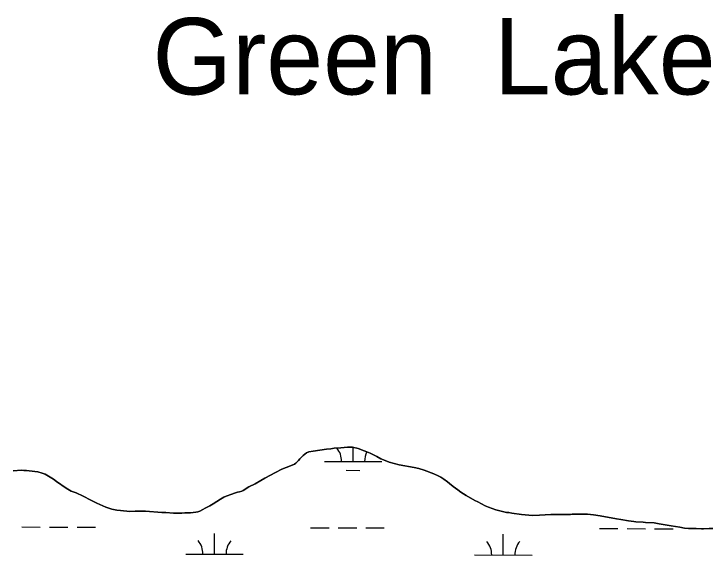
# Model space of a CAD drawing. Extents: x 3161615 to 3199515, y 867541 to 892976.
# Drawn here: x 3194005 to 3195219, y 874541 to 875483 of the extents above; entities that cross this region are included whole.
import ezdxf

# ---------------------------------------------------------------- set-up
doc = ezdxf.new("R2010")
doc.units = 0
for name, color, linetype in [('V-RIVR-IDEN', 7, 'Continuous'), ('V-SITE-VEGE', 7, 'Continuous'), ('V-TOPO-SHOR', 7, 'Continuous'), ('V-WETL-SWMP', 7, 'Continuous')]:
    doc.layers.add(name, color=color, linetype=linetype)

msp = doc.modelspace()

# ---------------------------------------------------------------- linework, layer by layer
at = {"layer": 'V-SITE-VEGE'}
for p, q in [((3194548.7, 874725.6), (3194525.2, 874722.4)), ((3194556.2, 874726.4), (3194548.7, 874725.6)), ((3194561.9, 874727.2), (3194556.2, 874726.4)), ((3194573.6, 874728.1), (3194561.9, 874727.2)), ((3194585, 874729.2), (3194573.6, 874728.1)), ((3194593.5, 874729), (3194585, 874729.2)), ((3194603.4, 874726.6), (3194593.5, 874729)), ((3194614, 874722.8), (3194603.4, 874726.6)), ((3194618.5, 874721), (3194614, 874722.8)), ((3194507.8, 874714.7), (3194502.2, 874709)), ((3194513.9, 874719), (3194507.8, 874714.7)), ((3194517.9, 874720.8), (3194513.9, 874719)), ((3194525.2, 874722.4), (3194517.9, 874720.8)), ((3194624.6, 874718.4), (3194618.5, 874721)), ((3194636.1, 874712.7), (3194624.6, 874718.4)), ((3194643.2, 874708.9), (3194636.1, 874712.7)), ((3194492.7, 874699.4), (3194485.8, 874696.5)), ((3194495.3, 874701), (3194492.7, 874699.4)), ((3194497.7, 874703.3), (3194495.3, 874701)), ((3194499.7, 874706.1), (3194497.7, 874703.3)), ((3194502.2, 874709), (3194499.7, 874706.1)), ((3194650.5, 874705.7), (3194643.2, 874708.9)), ((3194657.7, 874703.1), (3194650.5, 874705.7)), ((3194674.7, 874698.3), (3194657.7, 874703.1)), ((3194018.6, 874688.8), (3194004, 874688.2)), ((3194022.3, 874688.6), (3194018.6, 874688.8)), ((3194027.1, 874688.5), (3194022.3, 874688.6)), ((3194032, 874688.1), (3194027.1, 874688.5)), ((3194046.6, 874685.9), (3194032, 874688.1)), ((3194470.8, 874690.6), (3194459.7, 874685.3)), ((3194485.8, 874696.5), (3194470.8, 874690.6)), ((3194701.1, 874693.5), (3194674.7, 874698.3)), ((3194708.8, 874691.7), (3194701.1, 874693.5)), ((3194718.5, 874689.1), (3194708.8, 874691.7)), ((3194735.4, 874682.9), (3194718.5, 874689.1)), ((3194054.1, 874683.9), (3194046.6, 874685.9)), ((3194059.4, 874681.9), (3194054.1, 874683.9)), ((3194068.5, 874677.1), (3194059.4, 874681.9)), ((3194074.2, 874673.2), (3194068.5, 874677.1)), ((3194441.1, 874675.3), (3194434.2, 874671)), ((3194459.7, 874685.3), (3194441.1, 874675.3)), ((3194742.5, 874679.5), (3194735.4, 874682.9)), ((3194747.5, 874676.7), (3194742.5, 874679.5)), ((3194752.4, 874673.3), (3194747.5, 874676.7)), ((3194079.5, 874669.2), (3194074.2, 874673.2)), ((3194096, 874657.7), (3194079.5, 874669.2)), ((3194424.3, 874665.3), (3194413.6, 874660)), ((3194434.2, 874671), (3194424.3, 874665.3)), ((3194758.9, 874668.6), (3194752.4, 874673.3)), ((3194762.2, 874665.6), (3194758.9, 874668.6)), ((3194768.9, 874660.4), (3194762.2, 874665.6)), ((3194104.9, 874652.7), (3194096, 874657.7)), ((3194113.2, 874649.7), (3194104.9, 874652.7)), ((3194393.7, 874650.6), (3194388.5, 874649.1)), ((3194397.2, 874651.4), (3194393.7, 874650.6)), ((3194401.2, 874652.6), (3194397.2, 874651.4)), ((3194403.9, 874653.7), (3194401.2, 874652.6)), ((3194413.6, 874660), (3194403.9, 874653.7)), ((3194776.6, 874654.9), (3194768.9, 874660.4)), ((3194781.9, 874650.7), (3194776.6, 874654.9)), ((3194791.3, 874645), (3194781.9, 874650.7)), ((3194125.4, 874644.1), (3194113.2, 874649.7)), ((3194138.8, 874636.8), (3194125.4, 874644.1)), ((3194364.4, 874638.9), (3194351.5, 874630.7)), ((3194370.3, 874642.2), (3194364.4, 874638.9)), ((3194374.3, 874644), (3194370.3, 874642.2)), ((3194384.2, 874647.3), (3194374.3, 874644)), ((3194388.5, 874649.1), (3194384.2, 874647.3)), ((3194806.1, 874636.4), (3194791.3, 874645)), ((3194149.2, 874631.4), (3194138.8, 874636.8)), ((3194165, 874625), (3194149.2, 874631.4)), ((3194346, 874627.3), (3194337.9, 874623.2)), ((3194351.5, 874630.7), (3194346, 874627.3)), ((3194811.6, 874633.8), (3194806.1, 874636.4)), ((3194824.6, 874626.9), (3194811.6, 874633.8)), ((3194830, 874624.5), (3194824.6, 874626.9)), ((3194175.2, 874621.5), (3194165, 874625)), ((3194183.9, 874619.4), (3194175.2, 874621.5)), ((3194190.8, 874619), (3194183.9, 874619.4)), ((3194206.6, 874617.4), (3194190.8, 874619)), ((3194215.9, 874617.9), (3194206.6, 874617.4)), ((3194233.9, 874617.9), (3194215.9, 874617.9)), ((3194262.3, 874615.4), (3194233.9, 874617.9)), ((3194269.4, 874615.2), (3194262.3, 874615.4)), ((3194282.6, 874614.1), (3194269.4, 874615.2)), ((3194287.5, 874614.1), (3194282.6, 874614.1)), ((3194297, 874614.3), (3194287.5, 874614.1)), ((3194302.5, 874614.7), (3194297, 874614.3)), ((3194306.5, 874614.6), (3194302.5, 874614.7)), ((3194312.2, 874615), (3194306.5, 874614.6)), ((3194321.7, 874616), (3194312.2, 874615)), ((3194325, 874616.5), (3194321.7, 874616)), ((3194328.2, 874617.9), (3194325, 874616.5)), ((3194333.7, 874620.7), (3194328.2, 874617.9)), ((3194337.9, 874623.2), (3194333.7, 874620.7)), ((3194842.6, 874620.3), (3194830, 874624.5)), ((3194854.4, 874617.1), (3194842.6, 874620.3)), ((3194861.3, 874615.7), (3194854.4, 874617.1)), ((3194865.2, 874615.3), (3194861.3, 874615.7)), ((3194870.8, 874614.3), (3194865.2, 874615.3)), ((3194887.3, 874612.2), (3194870.8, 874614.3)), ((3194900.4, 874611), (3194887.3, 874612.2)), ((3194907.3, 874610.2), (3194900.4, 874611)), ((3194918.9, 874610.9), (3194907.3, 874610.2)), ((3194938.3, 874611.8), (3194918.9, 874610.9)), ((3194948.7, 874611.8), (3194938.3, 874611.8)), ((3194954.4, 874612), (3194948.7, 874611.8)), ((3194960.8, 874611.7), (3194954.4, 874612)), ((3194972.4, 874612.1), (3194960.8, 874611.7)), ((3194975.8, 874612.5), (3194972.4, 874612.1)), ((3194982.5, 874612.3), (3194975.8, 874612.5)), ((3194985.8, 874612.6), (3194982.5, 874612.3)), ((3195002, 874612.6), (3194985.8, 874612.6)), ((3195012.9, 874611.4), (3195002, 874612.6)), ((3195024.5, 874609.5), (3195012.9, 874611.4)), ((3195052.7, 874604.3), (3195024.5, 874609.5)), ((3195060, 874603.3), (3195052.7, 874604.3)), ((3195073.4, 874600.9), (3195060, 874603.3)), ((3195082.7, 874599.6), (3195073.4, 874600.9)), ((3195086.2, 874599.2), (3195082.7, 874599.6)), ((3195098.9, 874598.4), (3195086.2, 874599.2)), ((3195103, 874598), (3195098.9, 874598.4)), ((3195118.2, 874597.7), (3195103, 874598)), ((3195126.9, 874595.7), (3195118.2, 874597.7)), ((3195147.8, 874592.5), (3195126.9, 874595.7)), ((3195162.6, 874589.7), (3195147.8, 874592.5)), ((3195170.7, 874588.4), (3195162.6, 874589.7)), ((3195177.8, 874587.6), (3195170.7, 874588.4)), ((3195190.8, 874587.4), (3195177.8, 874587.6)), ((3195200.1, 874587), (3195190.8, 874587.4)), ((3195204, 874587.3), (3195200.1, 874587)), ((3195213.5, 874587.7), (3195204, 874587.3)), ((3195216.9, 874587.7), (3195213.5, 874587.7)), ((3195220.2, 874587.5), (3195216.9, 874587.7))]:
    msp.add_line(p, q, dxfattribs=at)
at = {"layer": 'V-TOPO-SHOR'}
for points in [[(3194585, 874729.2), (3194573.6, 874728.1), (3194561.9, 874727.2), (3194556.2, 874726.4), (3194548.7, 874725.6), (3194525.2, 874722.4), (3194517.9, 874720.8), (3194513.9, 874719), (3194507.8, 874714.7), (3194502.2, 874709), (3194499.7, 874706.1), (3194497.7, 874703.3), (3194495.3, 874701), (3194492.7, 874699.4), (3194485.8, 874696.5), (3194470.8, 874690.6), (3194459.7, 874685.3), (3194441.1, 874675.3), (3194434.2, 874671), (3194424.3, 874665.3), (3194413.6, 874660), (3194403.9, 874653.7), (3194401.2, 874652.6), (3194397.2, 874651.4), (3194393.7, 874650.6), (3194388.5, 874649.1), (3194384.2, 874647.3), (3194374.3, 874644), (3194370.3, 874642.2), (3194364.4, 874638.9), (3194351.5, 874630.7), (3194346, 874627.3), (3194337.9, 874623.2), (3194333.7, 874620.7), (3194328.2, 874617.9), (3194325, 874616.5), (3194321.7, 874616), (3194312.2, 874615), (3194306.5, 874614.6), (3194302.5, 874614.7), (3194297, 874614.3), (3194287.5, 874614.1), (3194282.6, 874614.1), (3194269.4, 874615.2), (3194262.3, 874615.4), (3194233.9, 874617.9), (3194215.9, 874617.9), (3194206.6, 874617.4), (3194190.8, 874619), (3194183.9, 874619.4), (3194175.2, 874621.5), (3194165, 874625), (3194149.2, 874631.4), (3194138.8, 874636.8), (3194125.4, 874644.1), (3194113.2, 874649.7), (3194104.9, 874652.7), (3194096, 874657.7), (3194079.5, 874669.2), (3194074.2, 874673.2), (3194068.5, 874677.1), (3194059.4, 874681.9), (3194054.1, 874683.9), (3194046.6, 874685.9), (3194032, 874688.1), (3194027.1, 874688.5), (3194022.3, 874688.6), (3194018.6, 874688.8), (3194004, 874688.2)], [(3195220.2, 874587.5), (3195216.9, 874587.7), (3195213.5, 874587.7), (3195204, 874587.3), (3195200.1, 874587), (3195190.8, 874587.4), (3195177.8, 874587.6), (3195170.7, 874588.4), (3195162.6, 874589.7), (3195147.8, 874592.5), (3195126.9, 874595.7), (3195118.2, 874597.7), (3195103, 874598), (3195098.9, 874598.4), (3195086.2, 874599.2), (3195082.7, 874599.6), (3195073.4, 874600.9), (3195060, 874603.3), (3195052.7, 874604.3), (3195024.5, 874609.5), (3195012.9, 874611.4), (3195002, 874612.6), (3194985.8, 874612.6), (3194982.5, 874612.3), (3194975.8, 874612.5), (3194972.4, 874612.1), (3194960.8, 874611.7), (3194954.4, 874612), (3194948.7, 874611.8), (3194938.3, 874611.8), (3194918.9, 874610.9), (3194907.3, 874610.2), (3194900.4, 874611), (3194887.3, 874612.2), (3194870.8, 874614.3), (3194865.2, 874615.3), (3194861.3, 874615.7), (3194854.4, 874617.1), (3194849.9, 874618.3), (3194842.6, 874620.3), (3194830, 874624.5), (3194824.6, 874626.9), (3194811.6, 874633.8), (3194806.1, 874636.4), (3194791.3, 874645), (3194781.9, 874650.7), (3194776.6, 874654.9), (3194768.9, 874660.4), (3194762.2, 874665.6), (3194758.9, 874668.6), (3194752.4, 874673.3), (3194747.5, 874676.7), (3194742.5, 874679.5), (3194735.4, 874682.9), (3194718.5, 874689.1), (3194708.8, 874691.7), (3194701.1, 874693.5), (3194674.7, 874698.3), (3194657.7, 874703.1), (3194650.5, 874705.7), (3194643.2, 874708.9), (3194636.1, 874712.7), (3194624.6, 874718.4), (3194618.5, 874721), (3194614, 874722.8), (3194603.4, 874726.6), (3194593.5, 874729), (3194585, 874729.2)]]:
    msp.add_lwpolyline(points, dxfattribs=at)
at = {"layer": 'V-WETL-SWMP'}
for p, q in [((3194525.2, 874722.4), (3194548.7, 874725.6)), ((3194548.7, 874725.6), (3194556.2, 874726.4)), ((3194556.2, 874726.4), (3194561.9, 874727.2)), ((3194561.9, 874727.2), (3194573.6, 874728.1)), ((3194573.6, 874728.1), (3194585, 874729.2)), ((3194585, 874729.2), (3194593.5, 874729)), ((3194593.5, 874729), (3194603.4, 874726.6)), ((3194594.8, 874704.2), (3194594.8, 874728.7)), ((3194603.4, 874726.6), (3194614, 874722.8)), ((3194614, 874722.8), (3194618.5, 874721)), ((3194502.2, 874709), (3194507.8, 874714.7)), ((3194507.8, 874714.7), (3194513.9, 874719)), ((3194513.9, 874719), (3194517.9, 874720.8)), ((3194517.9, 874720.8), (3194525.2, 874722.4)), ((3194618.5, 874721), (3194624.6, 874718.4)), ((3194624.6, 874718.4), (3194636.1, 874712.7)), ((3194636.1, 874712.7), (3194643.2, 874708.9)), ((3194485.8, 874696.5), (3194492.7, 874699.4)), ((3194492.7, 874699.4), (3194495.3, 874701)), ((3194495.3, 874701), (3194497.7, 874703.3)), ((3194497.7, 874703.3), (3194499.7, 874706.1)), ((3194499.7, 874706.1), (3194502.2, 874709)), ((3194544.8, 874704.3), (3194644.8, 874704)), ((3194643.2, 874708.9), (3194650.5, 874705.7)), ((3194650.5, 874705.7), (3194657.7, 874703.1)), ((3194657.7, 874703.1), (3194674.7, 874698.3)), ((3194004, 874688.2), (3194018.6, 874688.8)), ((3194018.6, 874688.8), (3194022.3, 874688.6)), ((3194022.3, 874688.6), (3194027.1, 874688.5)), ((3194027.1, 874688.5), (3194032, 874688.1)), ((3194032, 874688.1), (3194046.6, 874685.9)), ((3194459.7, 874685.3), (3194470.8, 874690.6)), ((3194470.8, 874690.6), (3194485.8, 874696.5)), ((3194582.7, 874688.8), (3194606.7, 874688.7)), ((3194674.7, 874698.3), (3194701.1, 874693.5)), ((3194701.1, 874693.5), (3194708.8, 874691.7)), ((3194708.8, 874691.7), (3194718.5, 874689.1)), ((3194718.5, 874689.1), (3194735.4, 874682.9)), ((3194046.6, 874685.9), (3194054.1, 874683.9)), ((3194054.1, 874683.9), (3194059.4, 874681.9)), ((3194059.4, 874681.9), (3194068.5, 874677.1)), ((3194068.5, 874677.1), (3194074.2, 874673.2)), ((3194434.2, 874671), (3194441.1, 874675.3)), ((3194441.1, 874675.3), (3194459.7, 874685.3)), ((3194735.4, 874682.9), (3194742.5, 874679.5)), ((3194742.5, 874679.5), (3194747.5, 874676.7)), ((3194747.5, 874676.7), (3194752.4, 874673.3)), ((3194074.2, 874673.2), (3194079.5, 874669.2)), ((3194079.5, 874669.2), (3194096, 874657.7)), ((3194413.6, 874660), (3194424.3, 874665.3)), ((3194424.3, 874665.3), (3194434.2, 874671)), ((3194752.4, 874673.3), (3194758.9, 874668.6)), ((3194758.9, 874668.6), (3194762.2, 874665.6)), ((3194762.2, 874665.6), (3194768.9, 874660.4)), ((3194096, 874657.7), (3194104.9, 874652.7)), ((3194104.9, 874652.7), (3194113.2, 874649.7)), ((3194388.5, 874649.1), (3194393.7, 874650.6)), ((3194393.7, 874650.6), (3194397.2, 874651.4)), ((3194397.2, 874651.4), (3194401.2, 874652.6)), ((3194401.2, 874652.6), (3194403.9, 874653.7)), ((3194403.9, 874653.7), (3194413.6, 874660)), ((3194768.9, 874660.4), (3194776.6, 874654.9)), ((3194776.6, 874654.9), (3194781.9, 874650.7)), ((3194781.9, 874650.7), (3194791.3, 874645)), ((3194113.2, 874649.7), (3194125.4, 874644.1)), ((3194125.4, 874644.1), (3194138.8, 874636.8)), ((3194351.5, 874630.7), (3194364.4, 874638.9)), ((3194364.4, 874638.9), (3194370.3, 874642.2)), ((3194370.3, 874642.2), (3194374.3, 874644)), ((3194374.3, 874644), (3194384.2, 874647.3)), ((3194384.2, 874647.3), (3194388.5, 874649.1)), ((3194791.3, 874645), (3194806.1, 874636.4)), ((3194138.8, 874636.8), (3194149.2, 874631.4)), ((3194149.2, 874631.4), (3194165, 874625)), ((3194337.9, 874623.2), (3194346, 874627.3)), ((3194346, 874627.3), (3194351.5, 874630.7)), ((3194806.1, 874636.4), (3194811.6, 874633.8)), ((3194811.6, 874633.8), (3194824.6, 874626.9)), ((3194824.6, 874626.9), (3194830, 874624.5)), ((3194165, 874625), (3194175.3, 874621.5)), ((3194175.3, 874621.5), (3194183.9, 874619.4)), ((3194183.9, 874619.4), (3194190.8, 874619)), ((3194190.8, 874619), (3194206.6, 874617.4)), ((3194206.6, 874617.4), (3194215.9, 874617.9)), ((3194215.9, 874617.9), (3194233.9, 874617.9)), ((3194233.9, 874617.9), (3194262.3, 874615.4)), ((3194262.3, 874615.4), (3194269.4, 874615.2)), ((3194269.4, 874615.2), (3194282.6, 874614.1)), ((3194282.6, 874614.1), (3194287.5, 874614.1)), ((3194287.5, 874614.1), (3194297, 874614.3)), ((3194297, 874614.3), (3194302.5, 874614.7)), ((3194302.5, 874614.7), (3194306.5, 874614.6)), ((3194306.5, 874614.6), (3194312.2, 874615)), ((3194312.2, 874615), (3194321.7, 874616)), ((3194321.7, 874616), (3194325, 874616.5)), ((3194325, 874616.5), (3194328.2, 874617.9)), ((3194328.2, 874617.9), (3194333.7, 874620.7)), ((3194333.7, 874620.7), (3194337.9, 874623.2)), ((3194830, 874624.5), (3194842.6, 874620.3)), ((3194842.6, 874620.3), (3194849.9, 874618.3)), ((3194849.9, 874618.3), (3194854.4, 874617.1)), ((3194854.4, 874617.1), (3194861.3, 874615.7)), ((3194861.3, 874615.7), (3194865.2, 874615.3)), ((3194865.2, 874615.3), (3194870.8, 874614.3)), ((3194870.8, 874614.3), (3194887.3, 874612.2)), ((3194887.3, 874612.2), (3194900.4, 874611)), ((3194900.4, 874611), (3194907.3, 874610.2)), ((3194907.3, 874610.2), (3194918.9, 874610.9)), ((3194918.9, 874610.9), (3194938.3, 874611.8)), ((3194938.3, 874611.8), (3194948.7, 874611.8)), ((3194948.7, 874611.8), (3194954.4, 874612)), ((3194954.4, 874612), (3194960.8, 874611.7)), ((3194960.8, 874611.7), (3194972.4, 874612.1)), ((3194972.4, 874612.1), (3194975.8, 874612.5)), ((3194975.8, 874612.5), (3194982.5, 874612.3)), ((3194982.5, 874612.3), (3194985.8, 874612.6)), ((3194985.8, 874612.6), (3195002, 874612.6)), ((3195002, 874612.6), (3195012.9, 874611.4)), ((3195012.9, 874611.4), (3195024.5, 874609.5)), ((3195024.5, 874609.5), (3195052.7, 874604.3)), ((3195052.7, 874604.3), (3195060, 874603.3)), ((3195060, 874603.3), (3195073.4, 874600.9)), ((3194019.1, 874590.3), (3194051.1, 874590.2)), ((3194067.1, 874590.2), (3194099.1, 874590.1)), ((3194115.1, 874590.1), (3194147.1, 874590)), ((3195073.4, 874600.9), (3195082.7, 874599.6)), ((3195082.7, 874599.6), (3195086.2, 874599.2)), ((3195086.2, 874599.2), (3195098.9, 874598.4)), ((3195098.9, 874598.4), (3195103, 874598)), ((3195103, 874598), (3195118.2, 874597.7)), ((3195118.2, 874597.7), (3195126.9, 874595.7)), ((3195126.9, 874595.7), (3195147.8, 874592.5)), ((3195147.8, 874592.5), (3195162.6, 874589.7)), ((3195162.6, 874589.7), (3195170.7, 874588.4)), ((3194353.9, 874543), (3194354, 874579)), ((3194521, 874588.9), (3194553, 874588.9)), ((3194569, 874588.8), (3194601, 874588.7)), ((3194617, 874588.7), (3194649, 874588.6)), ((3194855.8, 874541.6), (3194855.9, 874577.6)), ((3195022.9, 874587.6), (3195054.9, 874587.5)), ((3195070.9, 874587.4), (3195102.9, 874587.3)), ((3195118.9, 874587.3), (3195150.9, 874587.2)), ((3195170.7, 874588.4), (3195177.8, 874587.6)), ((3195177.8, 874587.6), (3195190.8, 874587.4)), ((3195190.8, 874587.4), (3195200.1, 874587)), ((3195200.1, 874587), (3195204, 874587.3)), ((3195204, 874587.3), (3195213.5, 874587.7)), ((3195213.5, 874587.7), (3195216.9, 874587.7)), ((3195216.9, 874587.7), (3195220.2, 874587.5)), ((3194303.9, 874543.1), (3194403.9, 874542.8)), ((3194805.8, 874541.7), (3194905.8, 874541.4))]:
    msp.add_line(p, q, dxfattribs=at)
for centre, start, end in [((3194539.5, 874704.8), 359.0699, 40.1526), ((3194650, 874704.5), 152.2571, 180.6135), ((3194298.6, 874543.6), 359.0699, 40.6135), ((3194409.1, 874543.3), 139.0699, 180.6135), ((3194800.5, 874542.2), 359.0699, 40.6135), ((3194911, 874541.9), 139.0699, 180.6135)]:
    msp.add_arc(centre, 35.2, start, end, dxfattribs=at)

# ---------------------------------------------------------------- texts
at = {"layer": 'V-RIVR-IDEN'}
msp.add_text('Green  Lake', height=133, dxfattribs=at).set_placement((3194246.2, 875342.5))

doc.saveas('drawing.dxf')
